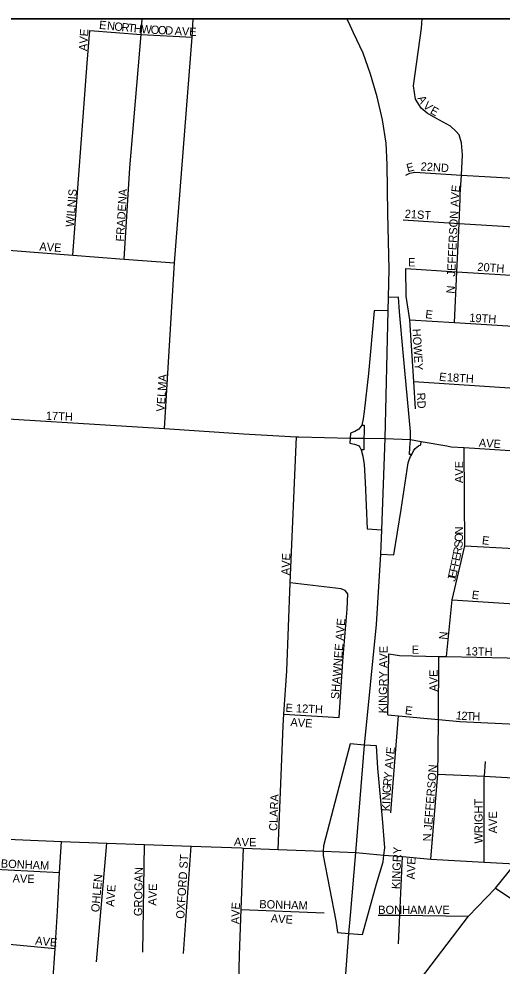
# Model space of a CAD drawing. Extents: x 0 to 34, y -6.2 to 22.
# Drawn here: x 7.114 to 7.668, y 20.104 to 21.19 of the extents above; entities that cross this region are included whole.
import ezdxf

# ---------------------------------------------------------------- set-up
doc = ezdxf.new("R2010")
doc.units = 0
for name, color, linetype in [('GM_X_City_Street', 7, 'Continuous'), ('GM_X_City_Street_Text', 7, 'Continuous'), ('GM_X_Corporation', 7, 'Continuous'), ('GM_X_Interchange_Ramps', 7, 'Continuous'), ('GM_X_Interstate_Route', 7, 'Continuous'), ('GM_X_State_Route', 7, 'Continuous'), ('GM_X_Township', 7, 'Continuous'), ('SH_Data', 7, 'Continuous')]:
    doc.layers.add(name, color=color, linetype=linetype)

msp = doc.modelspace()

# ---------------------------------------------------------------- linework, layer by layer
at = {"layer": 'GM_X_City_Street'}
for points in [[(7.2414, 21.0193), (7.2414, 21.0196), (7.2543, 21.1725), (7.2554, 21.1902)], [(7.2811, 20.7206), (7.2926, 20.9104), (7.3127, 21.1691), (7.3139, 21.1902)], [(7.6189, 21.0572), (7.6152, 21.0615), (7.609, 21.0674), (7.5923, 21.0764), (7.5823, 21.0822), (7.5753, 21.0878), (7.5689, 21.0983), (7.5668, 21.1135), (7.5759, 21.1796), (7.5765, 21.1902)], [(7.1924, 21.1393), (7.1952, 21.1769)], [(7.1952, 21.1769), (7.2543, 21.1725), (7.3127, 21.1691)], [(7.176, 20.9193), (7.1924, 21.1393)], [(7.6217, 21.0112), (7.6229, 21.0342), (7.6219, 21.0483), (7.6189, 21.0572)], [(7.2348, 20.9148), (7.2414, 21.0193)], [(7.5578, 21.011), (7.5625, 21.0135), (7.5682, 21.0144), (7.6217, 21.0112), (7.7954, 21.0011), (7.9233, 20.9957), (7.9583, 20.9916), (8.0246, 20.9876), (8.1566, 20.9814)], [(7.6139, 20.8421), (7.6165, 20.9002), (7.6189, 20.9557), (7.6202, 20.9838), (7.6204, 20.9889), (7.6217, 21.0112)], [(7.5547, 20.9598), (7.6189, 20.9557), (7.7009, 20.9505), (7.7918, 20.9446), (7.8584, 20.9404), (7.8837, 20.9388), (7.9343, 20.9383), (8.1293, 20.9267)], [(6.9729, 20.9348), (7.0427, 20.9295), (7.176, 20.9193), (7.2348, 20.9148), (7.2926, 20.9104)], [(7.5578, 20.9039), (7.6165, 20.9002), (7.6971, 20.8952), (7.788, 20.8896), (7.846, 20.886), (7.8551, 20.8854), (7.9306, 20.8806), (8.1019, 20.8718), (8.3017, 20.8561), (8.3726, 20.8513)], [(7.5689, 20.7431), (7.5672, 20.7744), (7.5624, 20.8452), (7.5583, 20.8721), (7.5578, 20.9039)], [(7.5624, 20.8452), (7.6139, 20.8421), (7.6932, 20.8373), (7.7841, 20.8319), (7.8221, 20.8296), (7.8517, 20.8278), (7.92, 20.8236), (8.0729, 20.8148)], [(7.5672, 20.7744), (7.6885, 20.7666), (7.7792, 20.7608), (7.8777, 20.7544), (7.9152, 20.7521), (8.0375, 20.7433), (8.1657, 20.7363), (8.2927, 20.7283), (8.3381, 20.7255)], [(6.7866, 20.7521), (6.7877, 20.752), (6.9377, 20.7427), (7.0333, 20.7357), (7.2811, 20.7206), (7.3663, 20.7149)], [(7.3663, 20.7149), (7.3715, 20.7146), (7.4323, 20.711), (7.4351, 20.7109)], [(7.4115, 20.2379), (7.4171, 20.3797), (7.418, 20.393), (7.4212, 20.4426), (7.4253, 20.5435), (7.4323, 20.711)], [(7.4351, 20.7109), (7.4941, 20.7095), (7.5097, 20.7093)], [(7.5097, 20.7093), (7.5343, 20.7091), (7.5632, 20.7079), (7.5754, 20.7058), (7.6049, 20.7005)], [(7.6049, 20.7005), (7.6098, 20.6996), (7.6248, 20.6987), (7.6837, 20.6951), (7.7743, 20.6898), (7.9105, 20.6818), (7.9486, 20.6796)], [(7.6045, 20.459), (7.611, 20.5242), (7.6256, 20.586), (7.6248, 20.6987)], [(7.6256, 20.586), (7.6825, 20.583), (7.7714, 20.5775), (7.9489, 20.5667)], [(7.4862, 20.5356), (7.4837, 20.5365), (7.4253, 20.5435)], [(7.4814, 20.3893), (7.4855, 20.4537), (7.4906, 20.5132), (7.4915, 20.531), (7.4882, 20.5349), (7.4864, 20.5356), (7.4862, 20.5356)], [(7.611, 20.5242), (7.6765, 20.52), (7.7276, 20.5168), (7.7643, 20.515), (7.9165, 20.507)], [(7.5372, 20.3923), (7.5385, 20.4621)], [(7.5385, 20.4621), (7.5505, 20.4602), (7.5959, 20.4592), (7.6045, 20.459), (7.674, 20.4574), (7.7647, 20.4553)], [(7.5949, 20.3506), (7.5953, 20.3869), (7.5959, 20.4592)], [(7.418, 20.393), (7.4814, 20.3893)], [(7.5372, 20.3923), (7.5496, 20.3911), (7.5953, 20.3869), (7.62, 20.3846), (7.6927, 20.3812), (7.8095, 20.377), (7.8303, 20.3754)], [(7.5433, 20.3141), (7.5433, 20.3141), (7.5496, 20.3911)], [(7.5864, 20.2268), (7.5947, 20.324), (7.5949, 20.3504), (7.5949, 20.3506)], [(7.6478, 20.3195), (7.648, 20.3218), (7.6494, 20.3386)], [(7.5947, 20.324), (7.648, 20.3218), (7.7582, 20.3153)], [(7.5405, 20.2798), (7.5433, 20.3141)], [(7.6479, 20.2232), (7.6478, 20.3192), (7.6478, 20.3195)], [(7.0262, 20.2529), (7.0739, 20.2508), (7.1627, 20.2469), (7.2147, 20.245), (7.2579, 20.2435), (7.3116, 20.2416), (7.3693, 20.2396), (7.3718, 20.2395), (7.4115, 20.2379), (7.4632, 20.2358), (7.5007, 20.2343), (7.5328, 20.2314), (7.5542, 20.2296), (7.5864, 20.2268), (7.6479, 20.2232), (7.6835, 20.2215)], [(7.1317, 19.7316), (7.1327, 19.7733), (7.1352, 19.7998), (7.1358, 19.8124), (7.1387, 19.8235), (7.1415, 19.8383), (7.1434, 19.8658), (7.146, 19.9606), (7.1503, 20.0463), (7.1555, 20.1243), (7.1583, 20.1672), (7.1607, 20.2115), (7.1627, 20.2469)], [(7.2029, 20.109), (7.2147, 20.245)], [(7.2562, 20.12), (7.2579, 20.2435)], [(7.3028, 20.1187), (7.3116, 20.2416)], [(7.3606, 19.8327), (7.3624, 19.9196), (7.3625, 19.926), (7.3672, 20.1165), (7.3691, 20.1689), (7.3718, 20.2395)], [(7.5495, 20.1296), (7.551, 20.1623), (7.5542, 20.2296)], [(7.0471, 20.2174), (7.0717, 20.2161), (7.1607, 20.2115)], [(7.6606, 20.1934), (7.7058, 20.1636), (7.7316, 20.1503), (7.7497, 20.1479), (7.811, 20.1445), (7.8545, 20.1421), (7.8988, 20.1397), (8.0252, 20.1327), (8.0721, 20.1301)], [(7.3691, 20.1689), (7.4641, 20.165)], [(7.5262, 20.1625), (7.551, 20.1623), (7.6299, 20.1615)], [(7.0663, 20.1325), (7.1555, 20.1243)]]:
    msp.add_lwpolyline(points, dxfattribs=at)
at = {"layer": 'GM_X_Corporation'}
msp.add_lwpolyline([(5.4833, 14.3902), (9.0755, 14.3902), (9.0755, 21.1902), (4.181, 21.1902)], dxfattribs=at)
at = {"layer": 'GM_X_Interchange_Ramps'}
for points in [[(7.5632, 20.7079), (7.5633, 20.7171), (7.555, 20.8078), (7.5508, 20.8545), (7.5496, 20.871), (7.538, 20.8709)], [(7.5376, 20.8557), (7.5215, 20.8556), (7.515, 20.7837), (7.51, 20.74), (7.5091, 20.7317), (7.5073, 20.7245), (7.5038, 20.7198), (7.4995, 20.7172), (7.4945, 20.7153), (7.4941, 20.7095)], [(7.5073, 20.7245), (7.51, 20.7243), (7.5099, 20.7163), (7.5097, 20.7093)], [(7.4941, 20.7095), (7.4938, 20.7036), (7.499, 20.7027), (7.5014, 20.702), (7.5039, 20.7006), (7.5053, 20.6993), (7.5068, 20.696), (7.5084, 20.6888), (7.51, 20.6791), (7.5113, 20.659), (7.5135, 20.6054), (7.5303, 20.6045)], [(7.5097, 20.7093), (7.5097, 20.7026), (7.5098, 20.6961), (7.5068, 20.696)], [(7.5291, 20.5765), (7.5443, 20.5757), (7.5527, 20.6278), (7.5606, 20.6811), (7.5616, 20.6846), (7.5633, 20.6885), (7.5646, 20.6906), (7.5667, 20.6951), (7.5687, 20.6975), (7.5704, 20.6991), (7.5725, 20.7005), (7.5752, 20.7018), (7.5754, 20.7058)], [(7.5646, 20.6906), (7.5621, 20.6908), (7.5626, 20.6989), (7.5632, 20.7079)], [(7.5105, 20.3575), (7.4941, 20.3588), (7.4633, 20.2418), (7.4632, 20.2358)], [(7.5328, 20.2314), (7.5338, 20.2397), (7.5311, 20.2732), (7.5259, 20.3309), (7.5243, 20.3565), (7.5105, 20.3575)], [(7.4632, 20.2358), (7.4631, 20.231), (7.4776, 20.1561), (7.4794, 20.1426), (7.4926, 20.1416)], [(7.4926, 20.1416), (7.5082, 20.1405), (7.5241, 20.1983), (7.5319, 20.2238), (7.5328, 20.2314)]]:
    msp.add_lwpolyline(points, dxfattribs=at)
at = {"layer": 'GM_X_Interstate_Route'}
for points in [[(7.5343, 20.7091), (7.5376, 20.8557), (7.538, 20.8709), (7.5387, 20.9033), (7.5373, 20.9672), (7.5366, 21.0231), (7.5354, 21.0479), (7.5312, 21.0744), (7.525, 21.101), (7.5172, 21.127), (7.5088, 21.151), (7.4979, 21.1744), (7.4922, 21.1869), (7.4902, 21.1902)], [(7.5007, 20.2343), (7.5105, 20.3575), (7.5243, 20.4956), (7.5291, 20.5765), (7.5303, 20.6045), (7.5343, 20.7091)], [(7.4944, 20.1622), (7.5007, 20.2343)], [(7.4806, 19.9736), (7.4806, 19.9736), (7.4854, 20.0441), (7.4926, 20.1416), (7.4944, 20.1622)]]:
    msp.add_lwpolyline(points, dxfattribs=at)
at = {"layer": 'GM_X_State_Route'}
msp.add_lwpolyline([(7.5487, 20.0559), (7.5562, 20.065), (7.6299, 20.1615), (7.6606, 20.1934), (7.6835, 20.2215), (7.7582, 20.3153), (7.7809, 20.34), (7.8095, 20.377), (7.865, 20.4446), (7.8881, 20.4703), (7.9165, 20.507), (7.9227, 20.5156), (7.9267, 20.5227), (7.9434, 20.5555), (7.9489, 20.5667), (7.9732, 20.6161), (7.9766, 20.6245), (8.0022, 20.6765)], dxfattribs=at)
at = {"layer": 'GM_X_Township'}
msp.add_line((9.0029, 21.1902), (4.1671, 21.1902), dxfattribs=at)
at = {"layer": 'SH_Data'}
msp.add_lwpolyline([(9.0755, 21.1902), (9.0755, 14.3902), (2.2755, 14.3902), (2.2755, 21.1902)], close=True, dxfattribs=at)

# ---------------------------------------------------------------- texts
at = {"layer": 'GM_X_City_Street_Text'}
for s, rotation, p in [('AVE', 86.0574, (7.192, 21.1531)), ('E', 354.197, (7.2056, 21.1789)), ('N', 354.1981, (7.2147, 21.178)), ('O', 354.2253, (7.223, 21.1771)), ('R', 354.1855, (7.2313, 21.1763)), ('T', 354.2223, (7.2388, 21.1755)), ('H', 354.4845, (7.2454, 21.1748)), ('W', 356.4922, (7.2541, 21.174)), ('O', 357.0091, (7.265, 21.1733)), ('O', 356.9826, (7.2733, 21.1729)), ('D', 356.9826, (7.2816, 21.1725)), ('A', 356.9826, (7.2925, 21.1719)), ('V', 356.9826, (7.3008, 21.1715)), ('E', 356.9987, (7.3091, 21.171)), ('A', 299.6744, (7.5708, 21.0992)), ('V', 317.2788, (7.5769, 21.0895)), ('E', 330.7171, (7.585, 21.0824)), ('E', 14.6548, (7.56, 21.0144)), ('22ND', 356.6354, (7.5747, 21.0164)), ('WILNIS', 85.3312, (7.177, 20.9514)), ('FRADENA', 86.5336, (7.2345, 20.9347)), ('E', 83.705, (7.6194, 20.991)), ('A', 89.2131, (7.6186, 20.9746)), ('V', 85.2073, (7.6187, 20.9827)), ('21ST', 356.1883, (7.5564, 20.9622)), ('JEFFERSON', 87.3072, (7.6145, 20.8947)), ('AVE', 356.0494, (7.1372, 20.9247)), ('E', 0, (7.5604, 20.9064)), ('20TH', 355.9114, (7.6397, 20.9014)), ('N', 84.2721, (7.6136, 20.8748)), ('E', 352.8783, (7.5798, 20.8472)), ('19TH', 356.419, (7.6305, 20.8431)), ('HOWEY', 273.3044, (7.5655, 20.8347)), ('VELMA', 86.4984, (7.2811, 20.7397)), ('E', 352.8783, (7.5956, 20.7755)), ('18TH', 356.4186, (7.6047, 20.7747)), ('RD', 273.011, (7.5705, 20.7614)), ('17TH', 357.2752, (7.1447, 20.7306)), ('AVE', 356.0494, (7.6414, 20.6997)), ('AVE', 90, (7.6236, 20.6579)), ('N', 90, (7.6236, 20.5991)), ('O', 87.9623, (7.6233, 20.5905)), ('E', 352.8817, (7.6448, 20.588)), ('R', 79.8116, (7.6211, 20.575)), ('S', 83.887, (7.6226, 20.5831)), ('AVE', 88.0261, (7.4245, 20.5522)), ('F', 77.7739, (7.6182, 20.5616)), ('E', 77.7739, (7.6196, 20.5681)), ('F', 77.7739, (7.6168, 20.5551)), ('J', 77.7739, (7.6145, 20.5445)), ('E', 77.7739, (7.6154, 20.5485)), ('E', 352.8817, (7.6331, 20.5255)), ('SHAWNEE AVE', 85.4263, (7.4811, 20.4098)), ('N', 84.2916, (7.6053, 20.4781)), ('KINGRY AVE', 89.3342, (7.5361, 20.3938)), ('E', 0, (7.5646, 20.4622)), ('13TH', 358.2112, (7.6263, 20.4606)), ('AVE', 90, (7.5945, 20.4188)), ('E 12TH', 357.3988, (7.4197, 20.3956)), ('E', 352.8783, (7.5565, 20.393)), ('1', 353.2701, (7.6149, 20.3872)), ('AVE', 356.0569, (7.4252, 20.3793)), ('2', 357.1247, (7.6214, 20.3865)), ('T', 357.6612, (7.6273, 20.3862)), ('H', 357.8927, (7.634, 20.3859)), ('AVE', 84.0895, (7.5428, 20.3298)), ('JEFFERSON', 85.4257, (7.5878, 20.2598)), ('Y', 82.5252, (7.5417, 20.3178)), ('G', 87.0044, (7.5405, 20.3022)), ('R', 84.6495, (7.541, 20.3104)), ('CLARA', 87.5601, (7.4103, 20.2589)), ('N', 87.0263, (7.5401, 20.2939)), ('K', 87.0263, (7.5395, 20.2814)), ('I', 87.0263, (7.5399, 20.2897)), ('WRIGHT', 90, (7.6461, 20.2446)), ('AVE', 90, (7.6624, 20.2563)), ('N', 90, (7.587, 20.2471)), ('A', 356.0405, (7.3605, 20.2422)), ('V', 358.4727, (7.3693, 20.2416)), ('E', 359.9457, (7.3779, 20.2414)), ('KINGRY', 87.8801, (7.5511, 20.1922)), ('BONHAM', 357.2313, (7.093, 20.2172)), ('OXFORD ST', 86.2841, (7.3036, 20.1581)), ('AVE', 88.0264, (7.5682, 20.2033)), ('GROGAN', 89.0258, (7.2553, 20.1613)), ('AVE', 358.0261, (7.1066, 20.2001)), ('OHLEN', 85.1332, (7.2061, 20.1656)), ('AVE', 86.0569, (7.2232, 20.1719)), ('AVE', 88.0186, (7.2716, 20.1733)), ('BONHAM', 358.1534, (7.3896, 20.1706)), ('V', 89.1475, (7.367, 20.1604)), ('E', 84.8575, (7.3671, 20.1686)), ('BONHAM', 0, (7.5262, 20.1639)), ('AVE', 0, (7.5829, 20.1639)), ('A', 89.8907, (7.367, 20.1521)), ('AVE', 356.0569, (7.4027, 20.1543)), ('AVE', 353.8878, (7.1323, 20.1289))]:
    msp.add_text(s, height=0.00947, rotation=rotation, dxfattribs=at).set_placement(p)

doc.saveas('drawing.dxf')
